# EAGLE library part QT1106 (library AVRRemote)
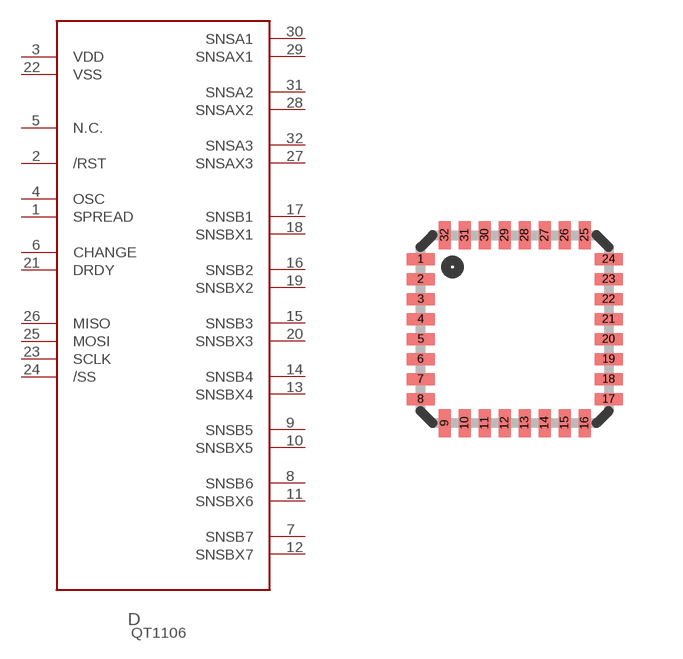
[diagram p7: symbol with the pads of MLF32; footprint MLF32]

Designator prefix D

## QT1106  [MLF32]
1  SPREAD
2  /RST
3  VDD
4  OSC
5  N.C.
6  CHANGE
7  SNSB7
8  SNSB6
9  SNSB5
10  SNSBX5
11  SNSBX6
12  SNSBX7
13  SNSBX4
14  SNSB4
15  SNSB3
16  SNSB2
17  SNSB1
18  SNSBX1
19  SNSBX2
20  SNSBX3
21  DRDY
22  VSS
23  SCLK
24  /SS
25  MOSI
26  MISO
27  SNSAX3
28  SNSAX2
29  SNSAX1
30  SNSA1
31  SNSA2
32  SNSA3

## Footprint MLF32 (pad centres in mm)
32M1-A Micro Lead Frame package (MLF)
smd 0.7 x 0.3: 1 -2.35,1.75; 2 -2.35,1.25; 3 -2.35,0.75; 4 -2.35,0.25; 5 -2.35,-0.25; 6 -2.35,-0.75; 7 -2.35,-1.25; 8 -2.35,-1.75; 17 2.35,-1.75; 18 2.35,-1.25; 19 2.35,-0.75; 20 2.35,-0.25; 21 2.35,0.25; 22 2.35,0.75; 23 2.35,1.25; 24 2.35,1.75
smd 0.3 x 0.7: 9 -1.75,-2.35; 10 -1.25,-2.35; 11 -0.75,-2.35; 12 -0.25,-2.35; 13 0.25,-2.35; 14 0.75,-2.35; 15 1.25,-2.35; 16 1.75,-2.35; 25 1.75,2.35; 26 1.25,2.35; 27 0.75,2.35; 28 0.25,2.35; 29 -0.25,2.35; 30 -0.75,2.35; 31 -1.25,2.35; 32 -1.75,2.35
